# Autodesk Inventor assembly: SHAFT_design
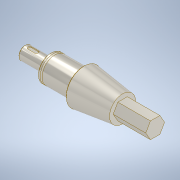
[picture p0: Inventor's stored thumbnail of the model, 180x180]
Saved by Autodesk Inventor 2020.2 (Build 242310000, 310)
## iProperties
Created: 2020-01
Part Number: SHAFT_design
Document SubType Name: Assembly
Designer: thira
Author: thira
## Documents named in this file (2)
- F:\99.โปรแกรมอัดหน้าจอ\Synergysoft\SHAFT_design.iam
- F:\99.โปรแกรมอัดหน้าจอ\Synergysoft\Shaft1.ipt
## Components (1 placed, 1 different names)
1. Shaft:1
